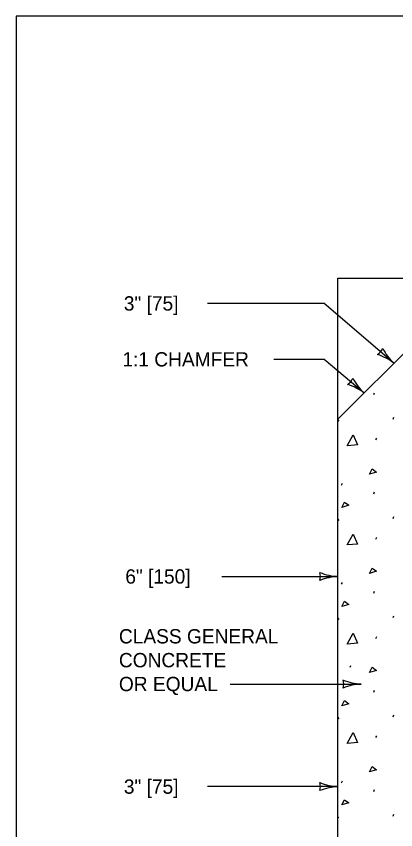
# Model space of a CAD drawing. Extents: x 49991.4 to 50021, y 49987.6 to 50011.4.
# Drawn here: x 50000.336 to 50001.927, y 50007.853 to 50011.263 of the extents above; entities that cross this region are included whole.
import ezdxf

# ---------------------------------------------------------------- set-up
doc = ezdxf.new("R2010")
doc.units = 0
for name, color, linetype in [('Level 1', 7, 'Continuous'), ('Level 2', 7, 'Continuous'), ('Level 3', 7, 'Continuous'), ('Level 4', 7, 'Continuous')]:
    doc.layers.add(name, color=color, linetype=linetype)

msp = doc.modelspace()

# ---------------------------------------------------------------- linework, layer by layer
at = {"layer": 'Level 1'}
for p, q in [((50001.6843, 50009.5741), (50002.275, 50010.1648)), ((50001.8344, 50009.6771), (50001.8379, 50009.6851)), ((50001.6843, 50007.6648), (50001.6843, 50009.5741)), ((50001.6843, 50009.5711), (50001.6879, 50009.5657)), ((50001.9152, 50009.5741), (50001.9187, 50009.5821)), ((50001.8433, 50009.4869), (50001.8468, 50009.4948)), ((50001.6994, 50009.2977), (50001.703, 50009.3057)), ((50001.8344, 50009.2613), (50001.8379, 50009.2693)), ((50001.6843, 50009.1553), (50001.6879, 50009.1499)), ((50001.9152, 50009.1583), (50001.9187, 50009.1663)), ((50001.8433, 50009.071), (50001.8468, 50009.079)), ((50001.6994, 50008.8819), (50001.703, 50008.8899)), ((50001.8344, 50008.8455), (50001.8379, 50008.8535)), ((50001.9152, 50008.7425), (50001.9187, 50008.7505)), ((50001.6843, 50008.7394), (50001.6879, 50008.7341)), ((50001.8433, 50008.6552), (50001.8468, 50008.6632)), ((50001.735, 50008.5341), (50001.7386, 50008.5421)), ((50001.8344, 50008.4297), (50001.8379, 50008.4377)), ((50001.6843, 50008.3236), (50001.6879, 50008.3183)), ((50001.9152, 50008.3267), (50001.9187, 50008.3346)), ((50001.8433, 50008.2394), (50001.8468, 50008.2474)), ((50001.6994, 50008.0503), (50001.703, 50008.0583)), ((50001.8344, 50008.0138), (50001.8379, 50008.0218)), ((50001.6843, 50007.9078), (50001.6879, 50007.9025)), ((50001.9152, 50007.9108), (50001.9187, 50007.9188))]:
    msp.add_line(p, q, dxfattribs=at)
msp.add_lwpolyline([(50008.6146, 50011.2628), (50000.3356, 50011.2628), (50000.3356, 50000.0624), (50008.6146, 50000.0624)], close=True, dxfattribs=at)
for points in [[(50001.7234, 50009.4629), (50001.7474, 50009.5082), (50001.766, 50009.4664), (50001.7243, 50009.4629)], [(50001.8168, 50009.3435), (50001.8275, 50009.3657), (50001.8452, 50009.3523), (50001.8168, 50009.3435)], [(50001.7012, 50009.2045), (50001.7118, 50009.2267), (50001.7296, 50009.2133), (50001.7012, 50009.2045)], [(50001.7234, 50009.0471), (50001.7474, 50009.0923), (50001.766, 50009.0506), (50001.7243, 50009.0471)], [(50001.8168, 50008.9276), (50001.8275, 50008.9498), (50001.8452, 50008.9365), (50001.8168, 50008.9276)], [(50001.7012, 50008.7886), (50001.7118, 50008.8108), (50001.7296, 50008.7975), (50001.7012, 50008.7886)], [(50001.7234, 50008.6312), (50001.7474, 50008.6765), (50001.766, 50008.6348), (50001.7243, 50008.6312)], [(50001.8168, 50008.5118), (50001.8275, 50008.534), (50001.8452, 50008.5207), (50001.8168, 50008.5118)], [(50001.7012, 50008.3728), (50001.7118, 50008.395), (50001.7296, 50008.3817), (50001.7012, 50008.3728)], [(50001.7234, 50008.2154), (50001.7474, 50008.2607), (50001.766, 50008.219), (50001.7243, 50008.2154)], [(50001.8168, 50008.096), (50001.8275, 50008.1182), (50001.8452, 50008.1049), (50001.8168, 50008.096)], [(50001.7012, 50007.957), (50001.7118, 50007.9792), (50001.7296, 50007.9659), (50001.7012, 50007.957)]]:
    msp.add_lwpolyline(points, dxfattribs=at)
at = {"layer": 'Level 3'}
for p, q in [((50001.626, 50010.0592), (50001.1376, 50010.0592)), ((50001.9187, 50009.8085), (50001.626, 50010.0592)), ((50001.626, 50009.8249), (50001.4154, 50009.8249)), ((50001.794, 50009.6838), (50001.626, 50009.8249)), ((50001.1976, 50008.9148), (50001.6843, 50008.9148)), ((50001.2321, 50008.4641), (50001.7818, 50008.4641)), ((50001.6843, 50008.0341), (50001.1376, 50008.0341))]:
    msp.add_line(p, q, dxfattribs=at)
for centre, radius, start, end in [((50001.8213, 50009.8919), 0.0548, 301.5585, 337.2808), ((50002.0702, 50009.9713), 0.2223, 206.8757, 227.0592), ((50001.776, 50009.6243), 0.233, 52.247, 71.4968), ((50001.6958, 50009.7663), 0.0548, 302.119, 337.8413), ((50001.9439, 50009.848), 0.2223, 207.4362, 227.6197), ((50001.6532, 50009.4982), 0.233, 52.8075, 72.0573), ((50001.6935, 50009.1369), 0.2223, 247.456, 267.6395), ((50001.5561, 50008.9148), 0.0548, 342.1388, 17.8612), ((50001.6958, 50008.6821), 0.233, 92.8273, 112.0772), ((50001.791, 50008.6862), 0.2223, 247.456, 267.6395), ((50001.6536, 50008.4641), 0.0548, 342.1388, 17.8612), ((50001.7933, 50008.2314), 0.233, 92.8273, 112.0772), ((50001.6935, 50008.2562), 0.2223, 247.456, 267.6395), ((50001.5561, 50008.0341), 0.0548, 342.1388, 17.8612), ((50001.6958, 50007.8014), 0.233, 92.8273, 112.0772)]:
    msp.add_arc(centre, radius, start, end, dxfattribs=at)
at = {"layer": 'Level 4'}
for p, q in [((50001.6843, 50009.5741), (50001.6843, 50010.1648)), ((50001.6843, 50010.1648), (50002.275, 50010.1648))]:
    msp.add_line(p, q, dxfattribs=at)

# ---------------------------------------------------------------- texts
at = {"layer": 'Level 2'}
for s, p in [('3" [75]', (50000.7865, 50010.0292)), ('1:1 CHAMFER', (50000.7805, 50009.7949)), ('6" [150]', (50000.7927, 50008.8848)), ('CLASS GENERAL', (50000.7659, 50008.6341)), ('CONCRETE ', (50000.7659, 50008.5341)), ('OR EQUAL', (50000.7659, 50008.4341)), ('3" [75]', (50000.7865, 50008.0041))]:
    msp.add_text(s, height=0.06, dxfattribs=at).set_placement(p)

doc.saveas('drawing.dxf')
